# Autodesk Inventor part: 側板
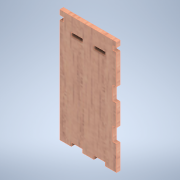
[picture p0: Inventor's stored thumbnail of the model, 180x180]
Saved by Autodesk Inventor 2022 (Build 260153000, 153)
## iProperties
Created: 2024-11
Part Number: 側板
Material: 木 (オーク)
Document SubType Name: Modeling
Designer: shimizu
Density: 0.76 g/cm^3
Appearance: ホワイト オーク材 - ナチュラル 標準の光沢
Author: shimizu
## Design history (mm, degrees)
sketch "スケッチ1"
  geometry: L1 (-20.243, 58.107)-(19.757, 58.107); L2 (-4.243, -21.893)-(-4.243, -19.393); L3 (-4.243, -19.393)-(-12.243, -19.393); L4 (-12.243, -19.393)-(-12.243, -21.893); L5 (11.757, -21.893)-(11.757, -19.393); L6 (11.757, -19.393)-(3.757, -19.393); L7 (3.757, -19.393)-(3.757, -21.893); L8 (-12.243, 48.107)-(-4.243, 48.107); L9 (-4.243, 48.107)-(-4.243, 45.607); L10 (-4.243, 45.607)-(-12.243, 45.607); L11 (-12.243, 45.607)-(-12.243, 48.107); L12 (3.757, 48.107)-(11.757, 48.107); L13 (11.757, 48.107)-(11.757, 45.607); L14 (11.757, 45.607)-(3.757, 45.607); L15 (3.757, 45.607)-(3.757, 48.107); L16 (-12.243, -21.893)-(-20.243, -21.893); L17 (19.757, -21.893)-(11.757, -21.893); L18 (3.757, -21.893)-(-4.243, -21.893); L19 (-20.243, 54.607)-(-17.743, 54.607); L20 (-17.743, 54.607)-(-17.743, 51.607); L21 (-17.743, 51.607)-(-20.243, 51.607); L22 (19.757, 54.607)-(17.257, 54.607); L23 (17.257, 54.607)-(17.257, 51.607); L24 (17.257, 51.607)-(19.757, 51.607); L25 (-20.243, -21.893)-(-20.243, 51.607); L26 (-20.243, 54.607)-(-20.243, 58.107); L27 (19.757, 58.107)-(19.757, 54.607); L28 (19.757, 51.607)-(19.757, -21.893); L29 (17.257, 30.607)-(19.757, 30.607); L30 (19.757, 30.607)-(19.757, 20.607); L31 (19.757, 20.607)-(17.257, 20.607); L32 (17.257, 20.607)-(17.257, 30.607); L33 (19.757, 5.607)-(17.257, 5.607); L34 (17.257, 5.607)-(17.257, -4.393); L35 (17.257, -4.393)-(19.757, -4.393); L36 (19.757, -4.393)-(19.757, 5.607); 3 further points
  constraints: 72 end point, 20 parallel, 9 perpendicular, 7 horizontal, 5 collinear, 2 point on line
  dimensions: "d27" = 80 distance between parallel lines of L17 L1; "d28" = 40 distance between parallel lines of L26 L27; "d29" = 10 distance between parallel lines of L31 L29; "d30" = 10 distance between parallel lines of L35 L33; "d31" = 2.5 distance of L30.end L31.end; "d32" = 2.5 distance of L34.end L35.end; "d33" = 15 distance between parallel lines of L6 L35; "d34" = 15 distance between parallel lines of L31 L33
extrude "押し出し1" new body sketch "スケッチ1" distance "d13" = 2.5; taper "d14" = 0 deg
node "ソリッド1"
